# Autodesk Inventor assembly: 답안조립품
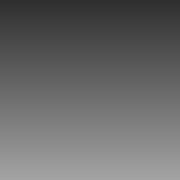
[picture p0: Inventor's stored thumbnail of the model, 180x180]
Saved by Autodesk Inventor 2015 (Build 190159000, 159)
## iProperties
Created: 2025-08
Part Number: 답안조립품
Document SubType Name: Assembly
Designer: USER
Author: USER
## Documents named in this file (1)
- C:\Users\USER\Desktop\750808V1015\답안조립품.iam
